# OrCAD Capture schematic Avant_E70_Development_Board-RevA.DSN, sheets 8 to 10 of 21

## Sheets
8 Bank-6 LED,SWITCH: size C; title: Bank-6 LED,SWITCH
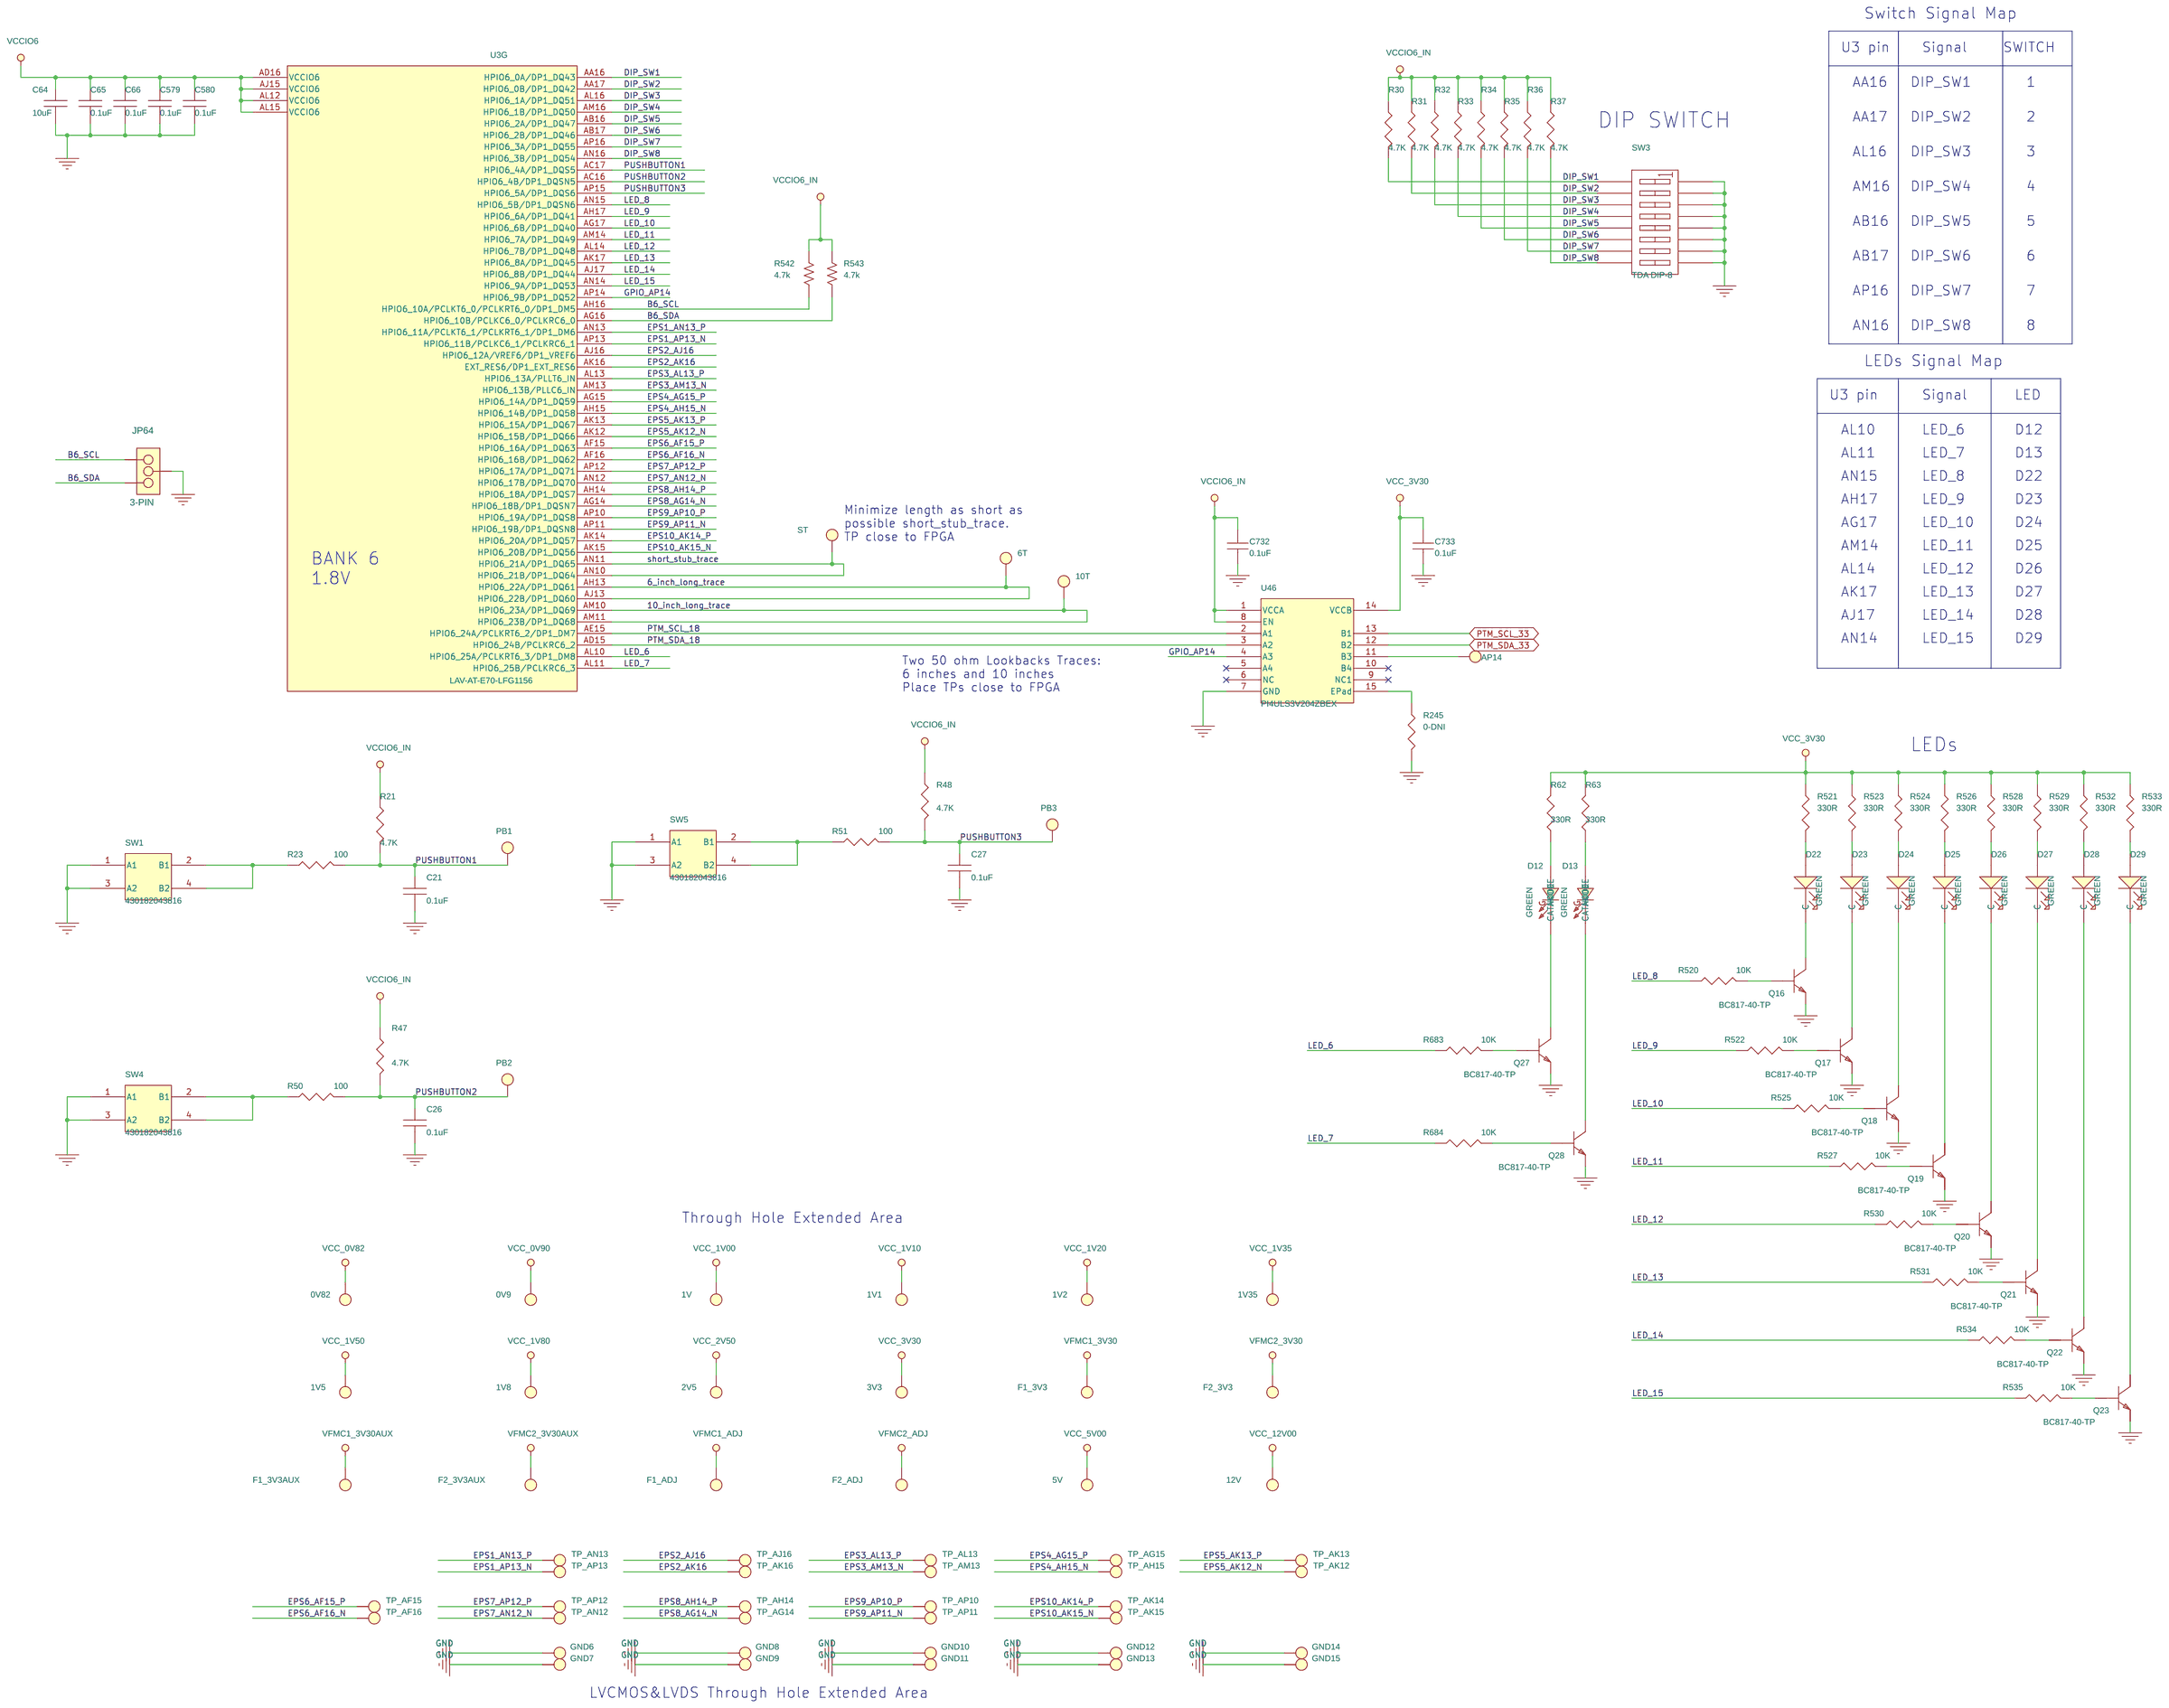
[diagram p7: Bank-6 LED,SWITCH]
9 Bank-7,8 FMC2: size B; title: Bank-7,8 FMC2
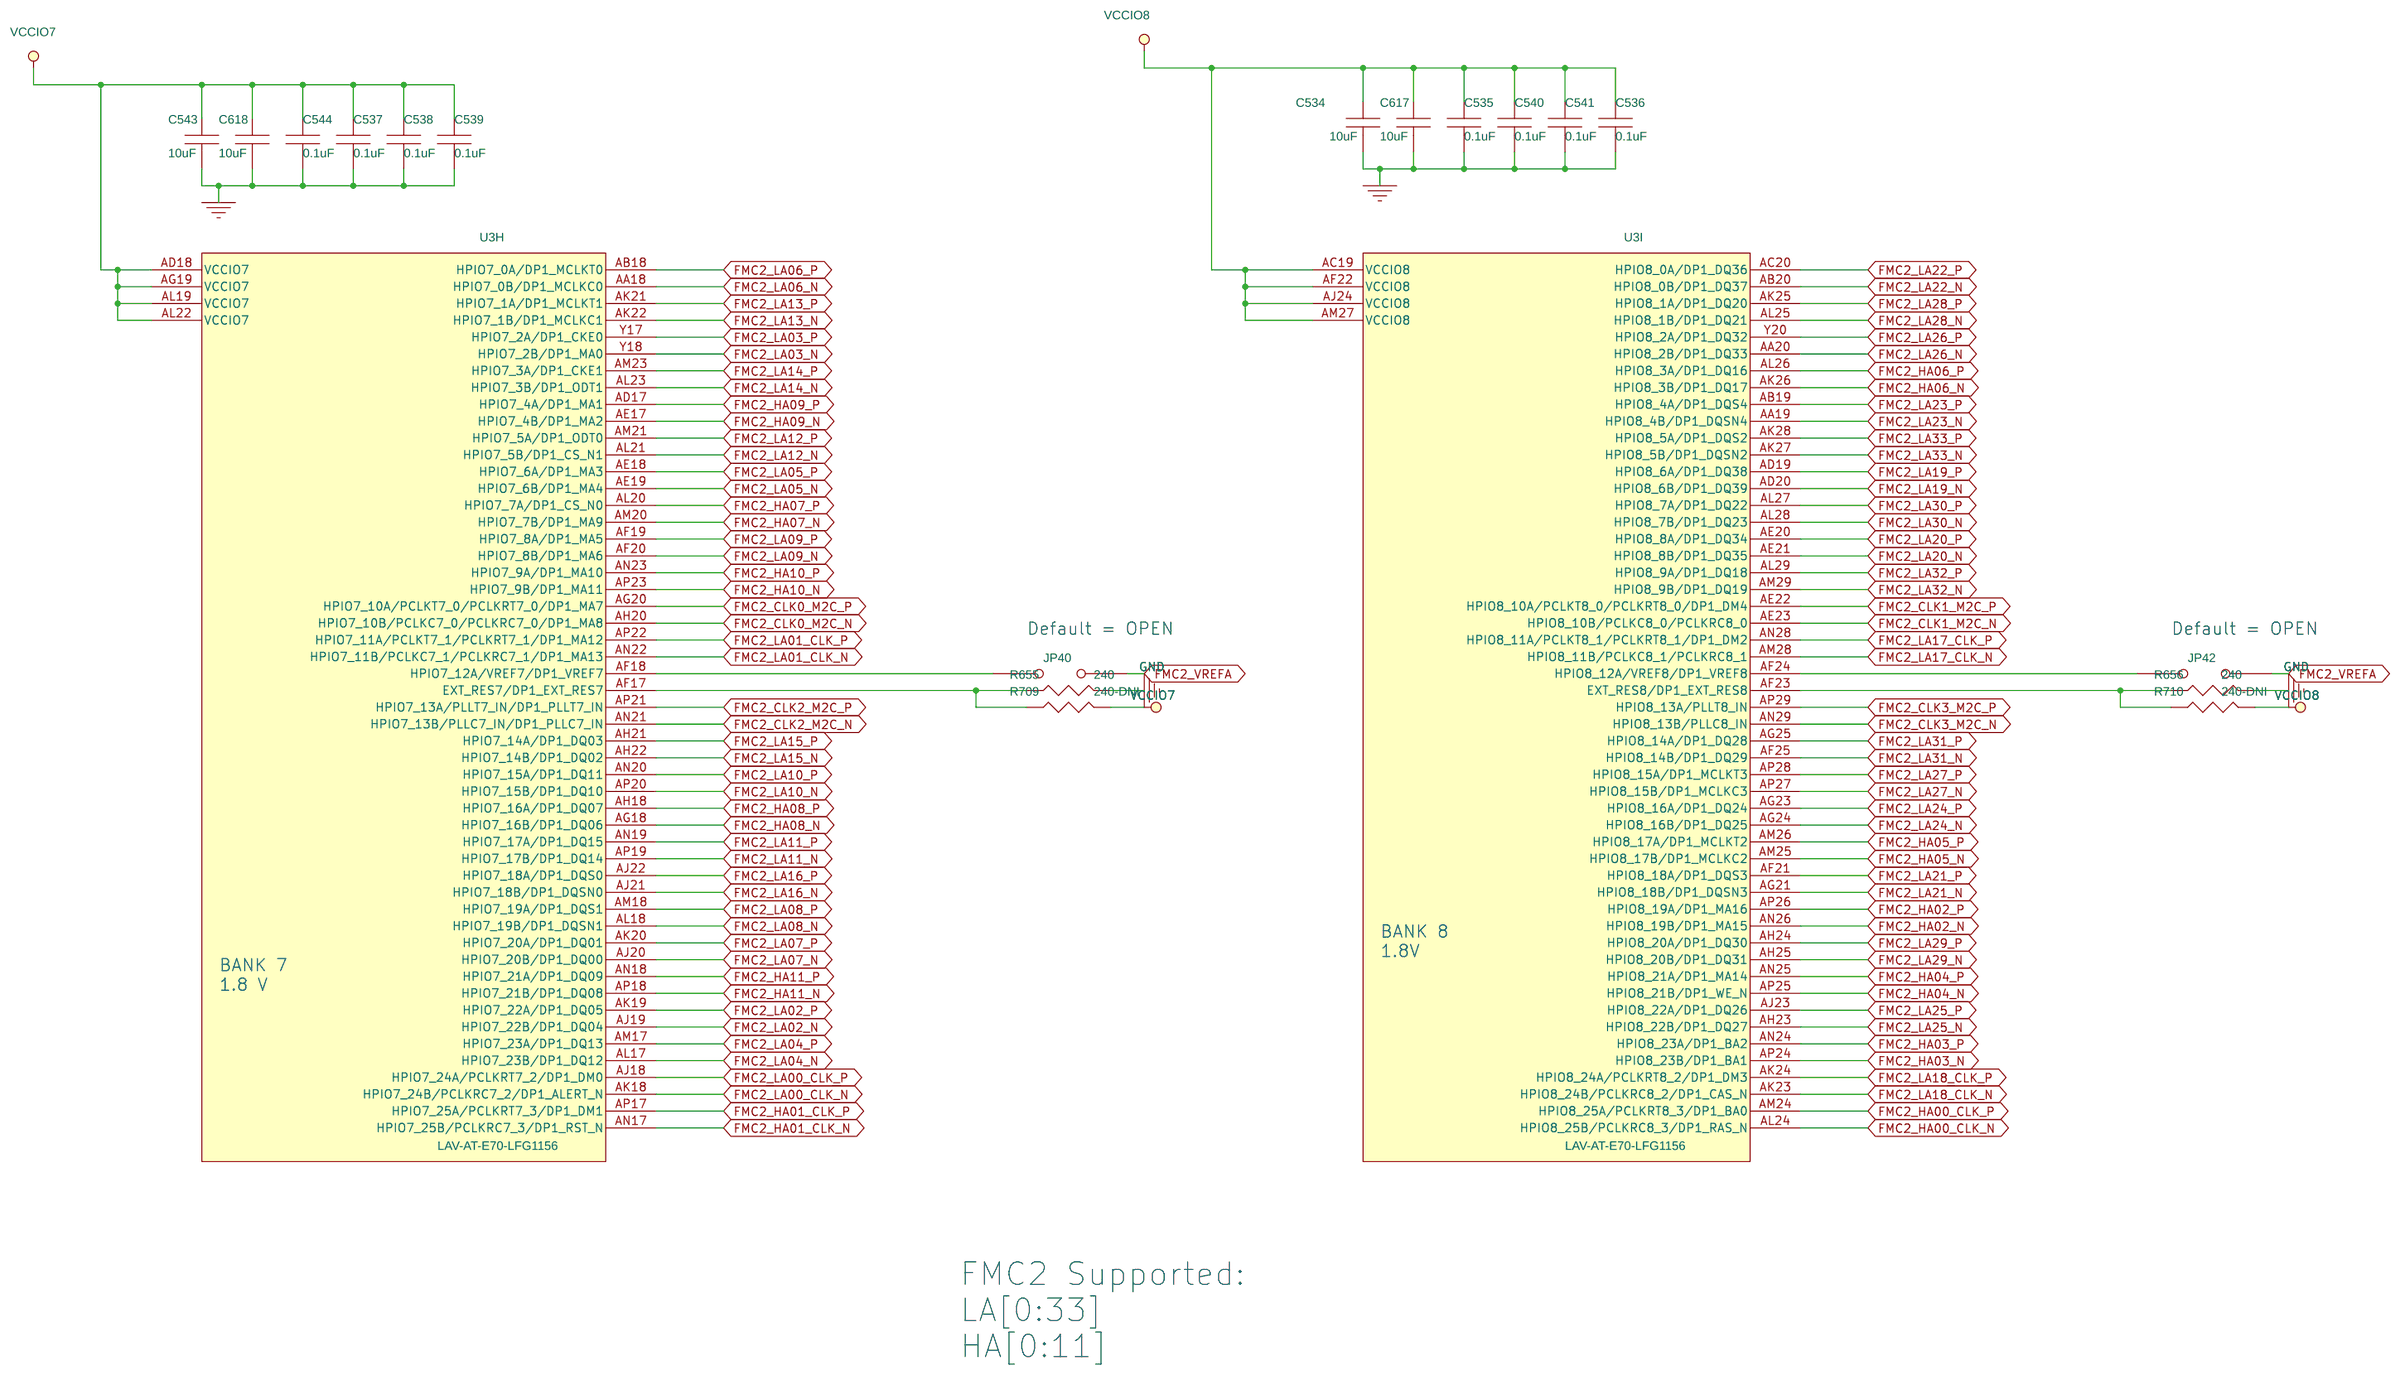
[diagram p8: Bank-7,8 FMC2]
10 FMC2 LA: size C; title: FMC2 LA
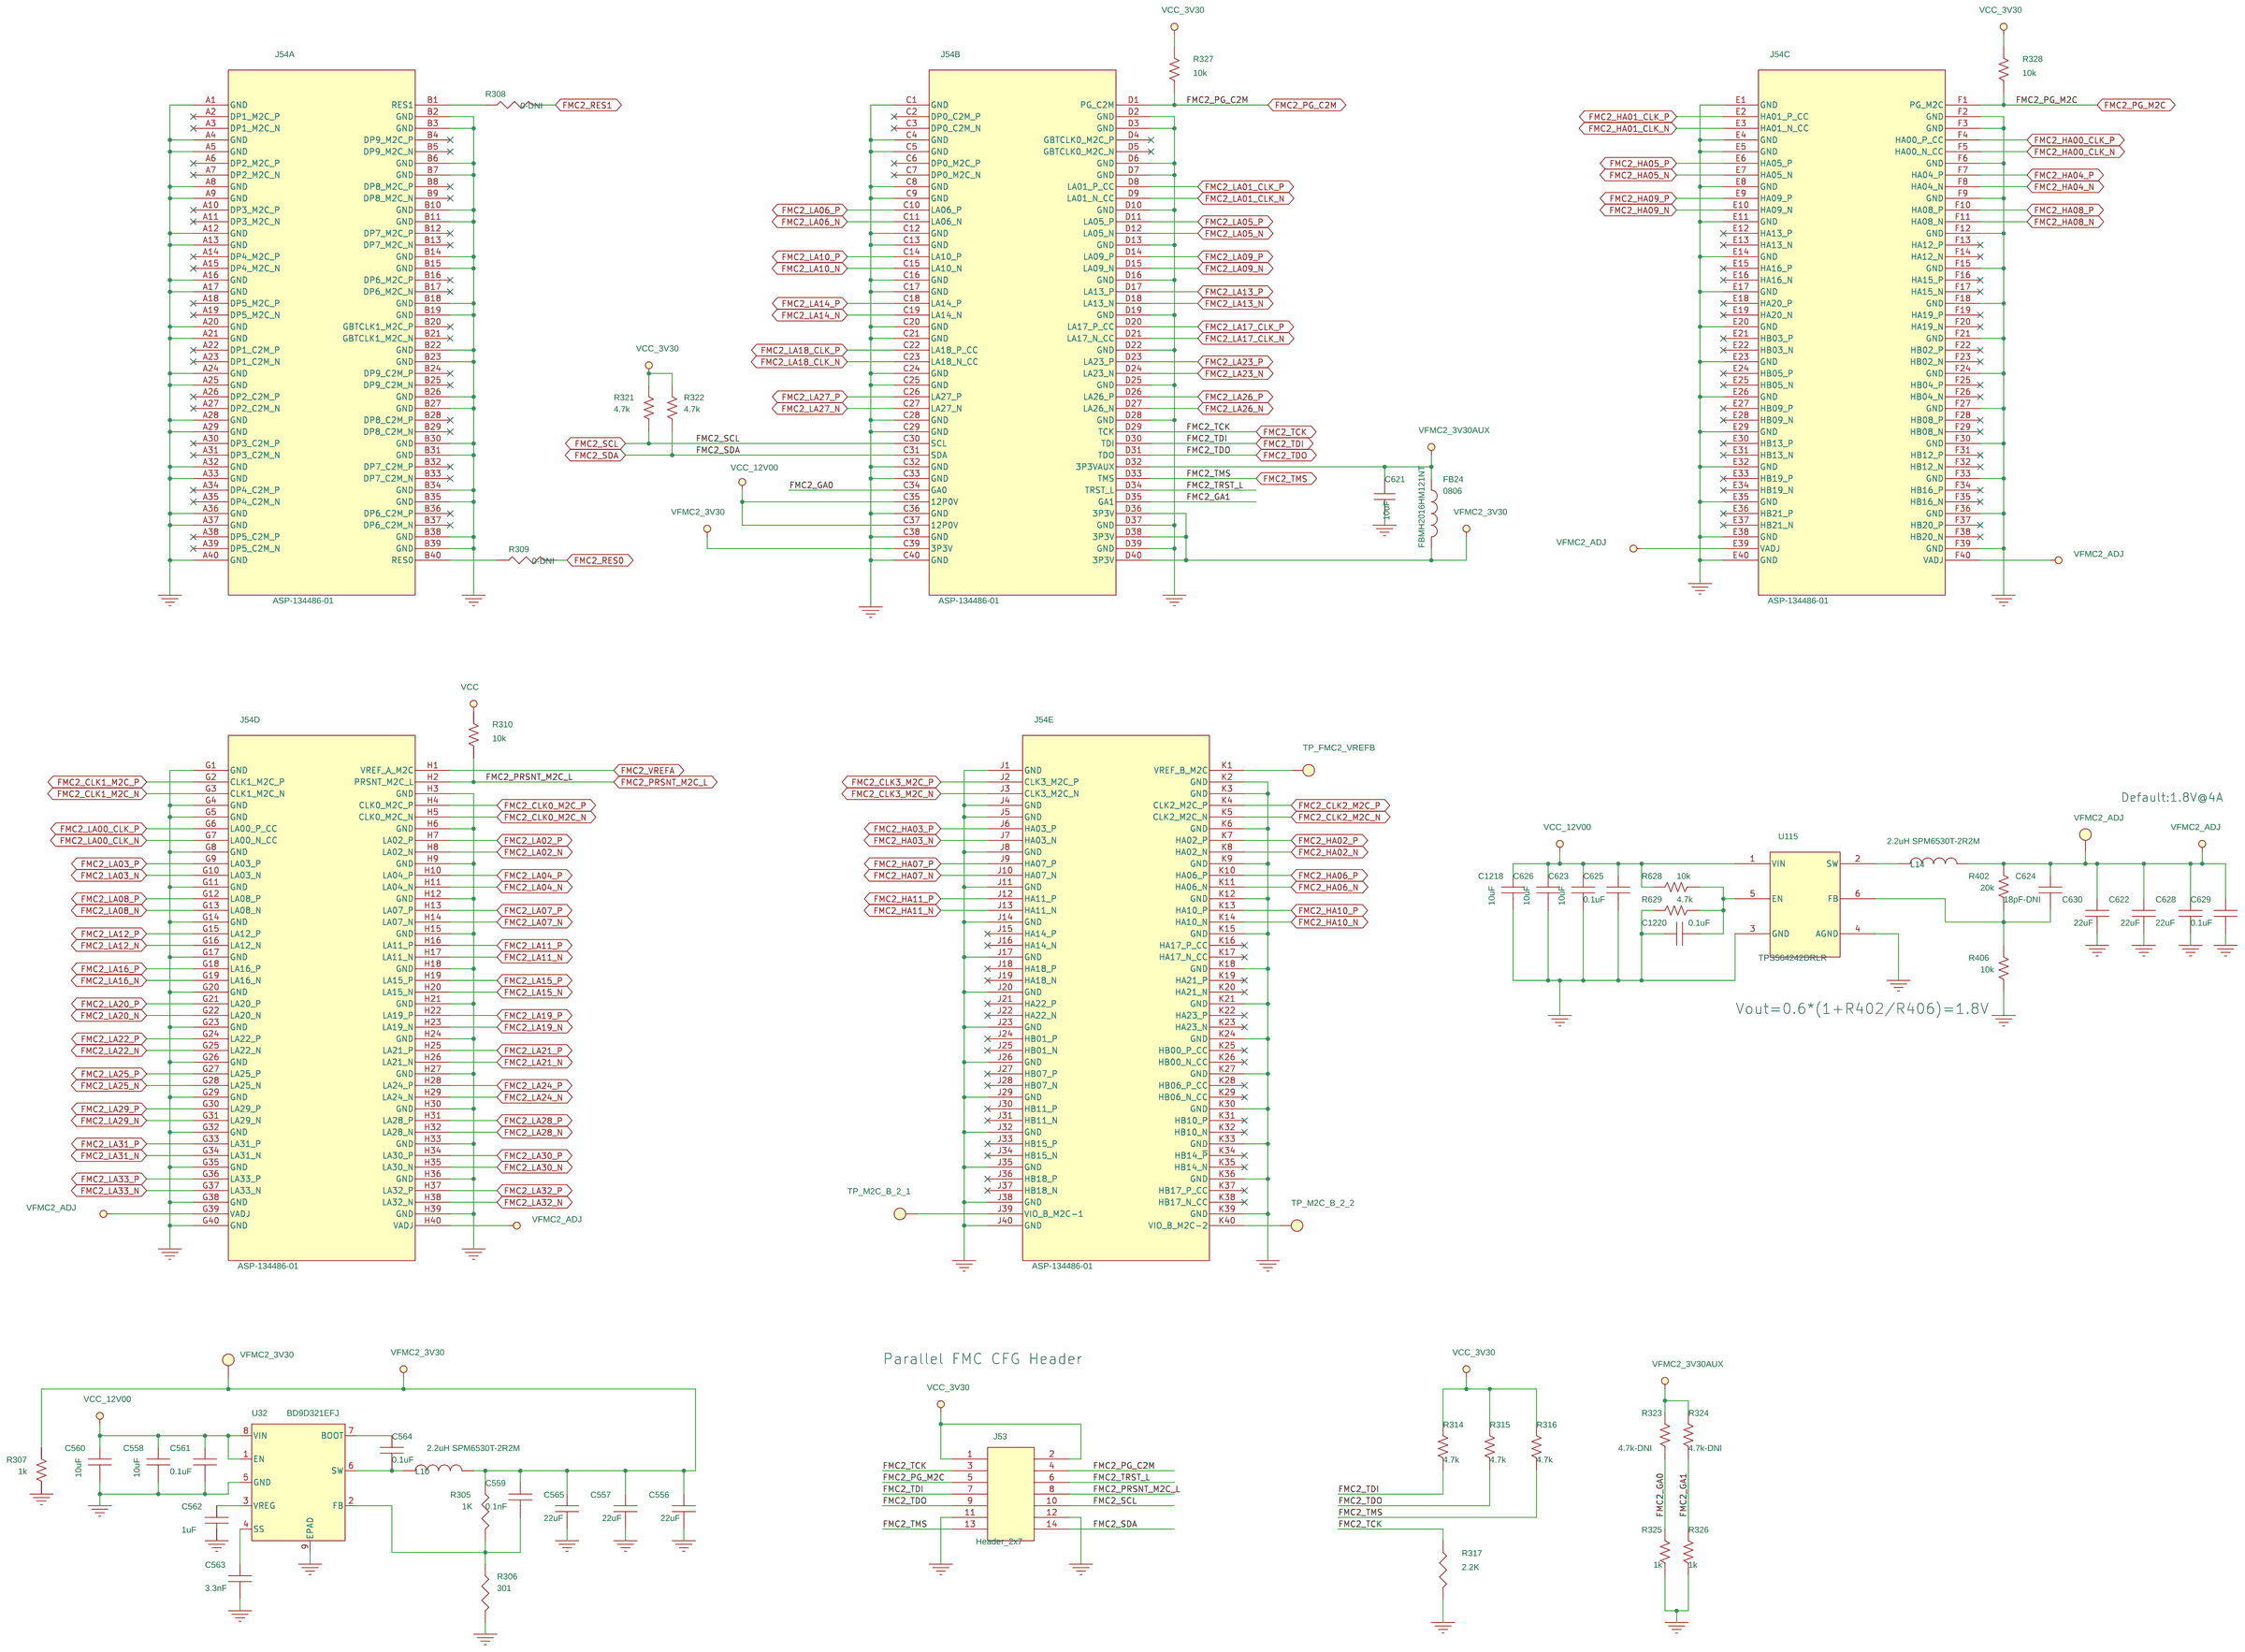
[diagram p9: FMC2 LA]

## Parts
sheet Bank-6 LED,SWITCH
0V9  T POINT R  [TP]
0V82  T POINT R  [TP]
1V  T POINT R  [TP]
1V1  T POINT R  [TP]
1V2  T POINT R  [TP]
1V5  T POINT R  [TP]
1V8  T POINT R  [TP]
1V35  T POINT R  [TP]
2V5  T POINT R  [TP]
3V3  T POINT R  [TP]
5V  T POINT R  [TP]
6T  VTTVREF  [TP_50]
10T  VTTVREF  [TP_50]
12V  T POINT R  [TP]
AP14  TestPoint_SMT  [TPC32]
C21  0.1uF  [C0201]
C26  0.1uF  [C0201]
C27  0.1uF  [C0201]
C64  10uF  [C0402]
C65  0.1uF  [C0201]
C66  0.1uF  [C0201]
C579  0.1uF  [C0201]
C580  0.1uF  [C0201]
C732  0.1uF  [C0402]
C733  0.1uF  [C0402]
D12  GREEN  [APT1608]
D13  GREEN  [APT1608]
D22  GREEN  [APT1608]
D23  GREEN  [APT1608]
D24  GREEN  [APT1608]
D25  GREEN  [APT1608]
D26  GREEN  [APT1608]
D27  GREEN  [APT1608]
D28  GREEN  [APT1608]
D29  GREEN  [APT1608]
F1_3V3  T POINT R  [TP]
F1_3V3AUX  T POINT R  [TP]
F1_ADJ  T POINT R  [TP]
F2_3V3  T POINT R  [TP]
F2_3V3AUX  T POINT R  [TP]
F2_ADJ  T POINT R  [TP]
GND6  T POINT R  [TP]
GND7  T POINT R  [TP]
GND8  T POINT R  [TP]
GND9  T POINT R  [TP]
GND10  T POINT R  [TP]
GND11  T POINT R  [TP]
GND12  T POINT R  [TP]
GND13  T POINT R  [TP]
GND14  T POINT R  [TP]
GND15  T POINT R  [TP]
JP64  3-PIN  [HDR254M-1X3]
PB1  TestPoint_SMT  [TPC32]
PB2  TestPoint_SMT  [TPC32]
PB3  TestPoint_SMT  [TPC32]
Q16  BC817-40-TP  [SOT23-3]
Q17  BC817-40-TP  [SOT23-3]
Q18  BC817-40-TP  [SOT23-3]
Q19  BC817-40-TP  [SOT23-3]
Q20  BC817-40-TP  [SOT23-3]
Q21  BC817-40-TP  [SOT23-3]
Q22  BC817-40-TP  [SOT23-3]
Q23  BC817-40-TP  [SOT23-3]
Q27  BC817-40-TP  [SOT23-3]
Q28  BC817-40-TP  [SOT23-3]
R21  4.7K  [R0603]
R23  100  [R0402]
R30  4.7K  [R0603]
R31  4.7K  [R0603]
R32  4.7K  [R0603]
R33  4.7K  [R0603]
R34  4.7K  [R0603]
R35  4.7K  [R0603]
R36  4.7K  [R0603]
R37  4.7K  [R0603]
R47  4.7K  [R0603]
R48  4.7K  [R0603]
R50  100  [R0402]
R51  100  [R0402]
R62  330R  [R0603]
R63  330R  [R0603]
R245  0-DNI  [R0402]
R520  10K  [R0603]
R521  330R  [R0603]
R522  10K  [R0603]
R523  330R  [R0603]
R524  330R  [R0603]
R525  10K  [R0603]
R526  330R  [R0603]
R527  10K  [R0603]
R528  330R  [R0603]
R529  330R  [R0603]
R530  10K  [R0603]
R531  10K  [R0603]
R532  330R  [R0603]
R533  330R  [R0603]
R534  10K  [R0603]
R535  10K  [R0603]
R542  4.7k  [R0603]
R543  4.7k  [R0603]
R683  10K  [R0603]
R684  10K  [R0603]
ST  VTTVREF  [TP_50]
SW1  430182043816  [430182043816]
SW3  TDA DIP-8  [TDA08H0SB1]
SW4  430182043816  [430182043816]
SW5  430182043816  [430182043816]
TP_AF15  T POINT R  [TP]
TP_AF16  T POINT R  [TP]
TP_AG14  T POINT R  [TP]
TP_AG15  T POINT R  [TP]
TP_AH14  T POINT R  [TP]
TP_AH15  T POINT R  [TP]
TP_AJ16  T POINT R  [TP]
TP_AK12  T POINT R  [TP]
TP_AK13  T POINT R  [TP]
TP_AK14  T POINT R  [TP]
TP_AK15  T POINT R  [TP]
TP_AK16  T POINT R  [TP]
TP_AL13  T POINT R  [TP]
TP_AM13  T POINT R  [TP]
TP_AN12  T POINT R  [TP]
TP_AN13  T POINT R  [TP]
TP_AP10  T POINT R  [TP]
TP_AP11  T POINT R  [TP]
TP_AP12  T POINT R  [TP]
TP_AP13  T POINT R  [TP]
U46  PI4ULS3V204ZBEX  [TQFN-14]
sheet Bank-7,8 FMC2
C534  10uF  [C0402]
C535  0.1uF  [C0201]
C536  0.1uF  [C0201]
C537  0.1uF  [C0201]
C538  0.1uF  [C0201]
C539  0.1uF  [C0201]
C540  0.1uF  [C0201]
C541  0.1uF  [C0201]
C543  10uF  [C0402]
C544  0.1uF  [C0201]
C617  10uF  [C0402]
C618  10uF  [C0402]
JP40  J-2 Pin Jumper  [0p1_2-Pin_TH]
JP42  J-2 Pin Jumper  [0p1_2-Pin_TH]
R655  240  [R0402]
R656  240  [R0402]
R709  240-DNI  [R0402]
R710  240-DNI  [R0402]
sheet Bank-12,13 PMODs
U3  LAV-AT-E70-LFG1156  [LAV-AT-500-L_1156]  (sections A,B,C,D,E,F,G,H,I,J,K,L,M,N,O,P,Q,R,S,T,U)
sheet FMC2 LA
C556  22uF  [C0603]
C557  22uF  [C0603]
C558  10uF  [C0603]
C559  0.1nF  [C0603]
C560  10uF  [C0603]
C561  0.1uF  [C0201]
C562  1uF  [C0603]
C563  3.3nF  [C0201]
C564  0.1uF  [C0201]
C565  22uF  [C0603]
C621  10uF  [C0402]
C622  22uF  [C0603]
C623  10uF  [C0603]
C624  18pF-DNI  [C0402]
C625  0.1uF  [C0201]
C626  10uF  [C0603]
C628  22uF  [C0603]
C629  0.1uF  [C0201]
C630  22uF  [C0603]
C1218  10uF  [C0603]
C1220  0.1uF  [C0201]
FB24  FBMH2016HM121NT  [0806]
J53  Header_2x7  [Header_2x7]
J54  ASP-134486-01  [ASP-134486-01]  (sections A,B,C,D,E)
L10  2.2uH SPM6530T-2R2M  [SPM6530T-2R2M]
L14  2.2uH SPM6530T-2R2M  [SPM6530T-2R2M]
R305  1K  [R0402]
R306  301  [R0402]
R307  1k  [R0603]
R308  0-DNI  [R0603]
R309  0-DNI  [R0603]
R310  10k  [R0603]
R314  4.7k  [R0603]
R315  4.7k  [R0603]
R316  4.7k  [R0603]
R317  2.2K  [R0603]
R321  4.7k  [R0603]
R322  4.7k  [R0603]
R323  4.7k-DNI  [R0603]
R324  4.7k-DNI  [R0603]
R325  1k  [R0603]
R326  1k  [R0603]
R327  10k  [R0603]
R328  10k  [R0603]
R402  20k  [R0603]
R406  10k  [R0603]
R628  10k  [R0603]
R629  4.7k  [R0603]
TP_FMC2_VREFB  TestPoint  [TP50]
TP_M2C_B_2_1  TestPoint  [TP50]
TP_M2C_B_2_2  TestPoint  [TP50]
U32  BD9D321EFJ  [HTSOP_8_BD9D321]
U115  TPS564242DRLR  [SOT-563-6]
VFMC2_3V30  VTTVREF  [TP_50]
VFMC2_ADJ  TestPoint_SMT  [TPC32]

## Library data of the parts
0V9 1V5 F2_3V3 = T_POINT_R_0: Assy: DNI; COMPFIXED: NO; COMPGROUP: 0; COMPHEIGHT: 0.000; COMPKEY: NO; COMPLOC: [400.000,3800.000]; COMPLOCKED: NO; COMPROT: 0; COMPSIDE: TOP; DECOUPLER: NO; MEMORY: NO
0V82 1V35 F1_3V3 = T_POINT_R_0: Assy: DNI; COMPFIXED: NO; COMPGROUP: 0; COMPHEIGHT: 0.000; COMPKEY: NO; COMPLOC: [300.000,3800.000]; COMPLOCKED: NO; COMPROT: 0; COMPSIDE: TOP; DECOUPLER: NO; MEMORY: NO
1V 1V8 5V TP_AK12 = T_POINT_R_0: Assy: DNI; COMPFIXED: NO; COMPGROUP: 0; COMPHEIGHT: 0.000; COMPKEY: NO; COMPLOC: [500.000,3800.000]; COMPLOCKED: NO; COMPROT: 0; COMPSIDE: TOP; DECOUPLER: NO; MEMORY: NO
1V1 1V2 2V5 3V3 12V F1_3V3AUX F1_ADJ F2_3V3AUX F2_ADJ = T_POINT_R_0: Assy: DNI; COMPFIXED: NO; COMPGROUP: 0; COMPHEIGHT: 0.000; COMPKEY: NO; COMPLOC: [700.000,3800.000]; COMPLOCKED: NO; COMPROT: 0; COMPSIDE: TOP; DECOUPLER: NO; MEMORY: NO
6T 10T ST VFMC2_3V30 = TP_SMD
AP14 PB1-PB3 VFMC2_ADJ = T_POINT_R: Assy: DNI
C21 C26 C27 = 0u1_0402: CAP CER 0.1UF 16V 10% X7R 0402
C64 C534 C543 C617 C618 = 10uF_0603
C65 C66 C535-C541 C544 C561 C564 C579 C580 C625 C629 C1220 = 0u1_0402: CAP CER 0.1UF 25V 10% X5R 0201; Manufacturer: Murata; Manufacturer Part Number: GRM033R61E104KE14J
C732 C733 = C-0402_0.1uF_10V_X5R_MURATA
D12 D13 = LED-SMT1206_GREEN_3
D22-D29 = D-_RED_LED_0: Manufacturer Part Number: 150060RS75000
GND6-GND15 = T_POINT_R_0: Assy: DNI; COMPFIXED: NO; COMPGROUP: 0; COMPHEIGHT: 0.000; COMPKEY: NO; COMPLOC: [300.000,3000.000]; COMPLOCKED: NO; COMPROT: 0; COMPSIDE: TOP; DECOUPLER: NO; MEMORY: NO
JP64 = 3-PINS_0.1_SINGLE_LINE_PIN
Q16-Q23 Q27 Q28 = TRANS_NPN_45V_0_0.8A_SOT-23: TRANS NPN 45V 0.8A SOT-23; Manufacturer: Micro Commercial Co
R21 R30-R37 R47 R48 = 5k1_0402: RES 4.70K OHM 1/10W 1% 0603 SMD; Digikey P/N: 541-4.70KHTR-ND; Manufacturer: Vishay; Manufacturer Part Number: CRCW06034K70FKEA
R23 R50 R51 = RES_10K_1W16_0402_5P: RES SMD 100 OHM 1% 1/10W 0402; Digikey P/N: RMCF0603JT10K0TR-ND; MFG: Pansonic; MFG P/N: ERJ-2RKF1000X; Manufacturer: Pansonic; Manufacturer Part Number: ERJ-2RKF1000X; Wattage: 1/10W
R62 R63 = 1k_0402: RES 1K OHM 1/10W 1% 0603 SMD; Digikey P/N: 311-1.00KHRCT-ND; Manufacturer Part Number: RC0603FR-071KL
R245 = R0402_0R_DNI_PANASONIC
R520 R522 R525 R527 R530 R531 R534 R535 R683 R684 = R_10K_0603: Manufacturer Part Number: RC1608F103CS
R521 R523 R524 R526 R528 R529 R532 R533 = R_330R_0603: Manufacturer Part Number: ERJ-3EKF3300V
R321 R542 = R: RES SMD 1K OHM 1% 1/10W 0402; COMPFIXED: NO; COMPGROUP: 0; COMPHEIGHT: 0.000; COMPKEY: NO; COMPLOC: [970.000,1160.000]; COMPLOCKED: NO; COMPROT: 180; COMPSIDE: TOP; DECOUPLER: NO; FPLIST: AX/RC05,SM/R_0603; MEMORY: NO; Manufacturer: Panasonic; Manufacturer Part Number: ERJ-2RKF1001X
R307 R310 R314-R316 R322-R328 R402 R406 R543 R628 R629 = R: RES SMD 4.7K OHM 5% 1/10W 0402; COMPFIXED: NO; COMPGROUP: 0; COMPHEIGHT: 0.000; COMPKEY: NO; COMPLOC: [970.000,1160.000]; COMPLOCKED: NO; COMPROT: 180; COMPSIDE: TOP; DECOUPLER: NO; FPLIST: AX/RC05,SM/R_0603; MEMORY: NO; MFG: Panasonic; MFG P/N: ERJ-2GEJ472X; Manufacturer: Panasonic; Manufacturer Part Number: ERJ-2GEJ472X
SW1 SW4 SW5 = EVQP0_0: SWITCH TACTILE SPST-NO 0.05A 12V; Cost Ea/1k: $ 0.11025 (1000-4999), 0.09135 (5000+); Digikey P/N: CKN9112TR-ND; Distributor: Digi-Key; MFG: C&K Components; Manufacturer: C&K Components
SW3 = SW_DIP-8
TP_AF15 = T_POINT_R_0: Assy: DNI; COMPFIXED: NO; COMPGROUP: 0; COMPHEIGHT: 0.000; COMPKEY: NO; COMPLOC: [500.000,3700.000]; COMPLOCKED: NO; COMPROT: 0; COMPSIDE: TOP; DECOUPLER: NO; MEMORY: NO
TP_AF16 = T_POINT_R_0: Assy: DNI; COMPFIXED: NO; COMPGROUP: 0; COMPHEIGHT: 0.000; COMPKEY: NO; COMPLOC: [500.000,3600.000]; COMPLOCKED: NO; COMPROT: 0; COMPSIDE: TOP; DECOUPLER: NO; MEMORY: NO
TP_AG14 TP_AK15 TP_AP11 = T_POINT_R_0: Assy: DNI; COMPFIXED: NO; COMPGROUP: 0; COMPHEIGHT: 0.000; COMPKEY: NO; COMPLOC: [500.000,3200.000]; COMPLOCKED: NO; COMPROT: 0; COMPSIDE: TOP; DECOUPLER: NO; MEMORY: NO
TP_AG15 = T_POINT_R_0: Assy: DNI; COMPFIXED: NO; COMPGROUP: 0; COMPHEIGHT: 0.000; COMPKEY: NO; COMPLOC: [600.000,3100.000]; COMPLOCKED: NO; COMPROT: 0; COMPSIDE: TOP; DECOUPLER: NO; MEMORY: NO
TP_AH14 TP_AK14 TP_AP10 = T_POINT_R_0: Assy: DNI; COMPFIXED: NO; COMPGROUP: 0; COMPHEIGHT: 0.000; COMPKEY: NO; COMPLOC: [500.000,3300.000]; COMPLOCKED: NO; COMPROT: 0; COMPSIDE: TOP; DECOUPLER: NO; MEMORY: NO
TP_AH15 = T_POINT_R_0: Assy: DNI; COMPFIXED: NO; COMPGROUP: 0; COMPHEIGHT: 0.000; COMPKEY: NO; COMPLOC: [600.000,3000.000]; COMPLOCKED: NO; COMPROT: 0; COMPSIDE: TOP; DECOUPLER: NO; MEMORY: NO
TP_AJ16 = T_POINT_R_0: Assy: DNI; COMPFIXED: NO; COMPGROUP: 0; COMPHEIGHT: 0.000; COMPKEY: NO; COMPLOC: [600.000,3500.000]; COMPLOCKED: NO; COMPROT: 0; COMPSIDE: TOP; DECOUPLER: NO; MEMORY: NO
TP_AK13 = T_POINT_R_0: Assy: DNI; COMPFIXED: NO; COMPGROUP: 0; COMPHEIGHT: 0.000; COMPKEY: NO; COMPLOC: [600.000,2900.000]; COMPLOCKED: NO; COMPROT: 0; COMPSIDE: TOP; DECOUPLER: NO; MEMORY: NO
TP_AK16 = T_POINT_R_0: Assy: DNI; COMPFIXED: NO; COMPGROUP: 0; COMPHEIGHT: 0.000; COMPKEY: NO; COMPLOC: [600.000,3400.000]; COMPLOCKED: NO; COMPROT: 0; COMPSIDE: TOP; DECOUPLER: NO; MEMORY: NO
TP_AL13 = T_POINT_R_0: Assy: DNI; COMPFIXED: NO; COMPGROUP: 0; COMPHEIGHT: 0.000; COMPKEY: NO; COMPLOC: [600.000,3300.000]; COMPLOCKED: NO; COMPROT: 0; COMPSIDE: TOP; DECOUPLER: NO; MEMORY: NO
TP_AM13 = T_POINT_R_0: Assy: DNI; COMPFIXED: NO; COMPGROUP: 0; COMPHEIGHT: 0.000; COMPKEY: NO; COMPLOC: [600.000,3200.000]; COMPLOCKED: NO; COMPROT: 0; COMPSIDE: TOP; DECOUPLER: NO; MEMORY: NO
TP_AN12 = T_POINT_R_0: Assy: DNI; COMPFIXED: NO; COMPGROUP: 0; COMPHEIGHT: 0.000; COMPKEY: NO; COMPLOC: [500.000,3400.000]; COMPLOCKED: NO; COMPROT: 0; COMPSIDE: TOP; DECOUPLER: NO; MEMORY: NO
TP_AN13 = T_POINT_R_0: Assy: DNI; COMPFIXED: NO; COMPGROUP: 0; COMPHEIGHT: 0.000; COMPKEY: NO; COMPLOC: [600.000,3700.000]; COMPLOCKED: NO; COMPROT: 0; COMPSIDE: TOP; DECOUPLER: NO; MEMORY: NO
TP_AP12 = T_POINT_R_0: Assy: DNI; COMPFIXED: NO; COMPGROUP: 0; COMPHEIGHT: 0.000; COMPKEY: NO; COMPLOC: [500.000,3500.000]; COMPLOCKED: NO; COMPROT: 0; COMPSIDE: TOP; DECOUPLER: NO; MEMORY: NO
TP_AP13 = T_POINT_R_0: Assy: DNI; COMPFIXED: NO; COMPGROUP: 0; COMPHEIGHT: 0.000; COMPKEY: NO; COMPLOC: [600.000,3600.000]; COMPLOCKED: NO; COMPROT: 0; COMPSIDE: TOP; DECOUPLER: NO; MEMORY: NO
U46 = U-PI4ULS3V204ZBEX
JP40 JP42 = J-2_Pin_Jumper: Manufacturer Part Number: 22-28-4020
R655 R656 R709 R710 = 0R_0603: RES 0.0 OHM 1/10W JUMP 0603 SMD
U3 = LAV-AT-E70-LFG1156_6
C556 C557 C565 C622 C630 = 10uF_0603: CAP CER 22UF 10V X5R 0603; Manufacturer: Murata; Manufacturer Part Number: GRM188R61A226ME15D
C558 C560 C623 C626 C1218 = 10uF_0603: CAP CER 10UF 25V X5R 1206; Manufacturer Part Number: TMK316BJ106KL-T
C559 C624 = 10uF_0603: CAP CER 100PF 50V C0G/NPO 0603; Manufacturer: Yageo; Manufacturer Part Number: CC0603JRNPO9BN101
C562 C628 = 10uF_0603: CAP CER 1UF 25V 10% X7R 0603; Manufacturer Part Number: TMK107B7105KA-T
C563 = 0u1_0402: CAP CER 3300PF 25V X7R 0201; Manufacturer: Murata; Manufacturer Part Number: GRM033R71E332KA12D
C621 = CAP_NP: COMPFIXED: NO; COMPGROUP: 0; COMPHEIGHT: 0.000; COMPKEY: NO; COMPLOC: [1820.000,2015.000]; COMPLOCKED: NO; COMPROT: 270; COMPSIDE: TOP; DECOUPLER: NO; FPLIST: SM/C_0402; MEMORY: NO
FB24 = FB_0806_120R_TaiyoYuden
J53 = Header_2x7
J54 = ASP-134486-01_0
L10 L14 = INDUCTOR_0
R305 = R0402_1K_1%_Yageo: Manufacturer Part Number: RC0402FR-071KL
R306 = R0402_301R_1%_Yageo: Manufacturer Part Number: RC0402FR-07301RL
R308 R309 R317 = 5k1_0402: Digikey P/N: 541-2.20KHTR-ND; Manufacturer: Vishay; Manufacturer Part Number: CRCW06032K20FKEA
TP_FMC2_VREFB TP_M2C_B_2_1 TP_M2C_B_2_2 = T_POINT_R
U32 = BD9D321EFJ
U115 = TPS564242DRLR

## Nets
GND: C21.2 C26.2 C27.2 C64.2 C65.2 C66.2 C534.2 C535.2 C536.2 C537.2 C538.2 C539.2 C540.2 C541.2 C543.2 C544.2 C556.2 C557.2 C558.2 C560.2 C561.2 C562.2 C563.2 C565.2 C579.2 C580.2 C617.2 C618.2 C621.1 C622.2 C623.2 C625.2 C626.2 C628.2 C629.2 C630.2 C732.2 C733.2 C1218.2 C1220.1 GND6.1(TP) GND7.1(TP) GND8.1(TP) GND9.1(TP) GND10.1(TP) GND11.1(TP) GND12.1(TP) GND13.1(TP) GND14.1(TP) GND15.1(TP) J53.11 J53.12 J54.A1(GND) J54.A4(GND) J54.A5(GND) J54.A8(GND) J54.A9(GND) J54.A12(GND) J54.A13(GND) J54.A16(GND) J54.A17(GND) J54.A20(GND) J54.A21(GND) J54.A24(GND) J54.A25(GND) J54.A28(GND) J54.A29(GND) J54.A32(GND) J54.A33(GND) J54.A36(GND) J54.A37(GND) J54.A40(GND) J54.B2(GND) J54.B3(GND) J54.B6(GND) J54.B7(GND) J54.B10(GND) J54.B11(GND) J54.B14(GND) J54.B15(GND) J54.B18(GND) J54.B19(GND) J54.B22(GND) J54.B23(GND) J54.B26(GND) J54.B27(GND) J54.B30(GND) J54.B31(GND) J54.B34(GND) J54.B35(GND) J54.B38(GND) J54.B39(GND) J54.C1(GND) J54.C4(GND) J54.C5(GND) J54.C8(GND) J54.C9(GND) J54.C12(GND) J54.C13(GND) J54.C16(GND) J54.C17(GND) J54.C20(GND) J54.C21(GND) J54.C24(GND) J54.C25(GND) J54.C28(GND) J54.C29(GND) J54.C32(GND) J54.C33(GND) J54.C36(GND) J54.C38(GND) J54.C40(GND) J54.D2(GND) J54.D3(GND) J54.D6(GND) J54.D7(GND) J54.D10(GND) J54.D13(GND) J54.D16(GND) J54.D19(GND) J54.D22(GND) J54.D25(GND) J54.D28(GND) J54.D37(GND) J54.D39(GND) J54.E1(GND) J54.E4(GND) J54.E5(GND) J54.E8(GND) J54.E11(GND) J54.E14(GND) J54.E17(GND) J54.E20(GND) J54.E23(GND) J54.E26(GND) J54.E29(GND) J54.E32(GND) J54.E35(GND) J54.E38(GND) J54.E40(GND) J54.F2(GND) J54.F3(GND) J54.F6(GND) J54.F9(GND) J54.F12(GND) J54.F15(GND) J54.F18(GND) J54.F21(GND) J54.F24(GND) J54.F27(GND) J54.F30(GND) J54.F33(GND) J54.F36(GND) J54.F39(GND) J54.G1(GND) J54.G4(GND) J54.G5(GND) J54.G8(GND) J54.G11(GND) J54.G14(GND) J54.G17(GND) J54.G20(GND) J54.G23(GND) J54.G26(GND) J54.G29(GND) J54.G32(GND) J54.G35(GND) J54.G38(GND) J54.G40(GND) J54.H3(GND) J54.H6(GND) J54.H9(GND) J54.H12(GND) J54.H15(GND) J54.H18(GND) J54.H21(GND) J54.H24(GND) J54.H27(GND) J54.H30(GND) J54.H33(GND) J54.H36(GND) J54.H39(GND) J54.J1(GND) J54.J4(GND) J54.J5(GND) J54.J8(GND) J54.J11(GND) J54.J14(GND) J54.J17(GND) J54.J20(GND) J54.J23(GND) J54.J26(GND) J54.J29(GND) J54.J32(GND) J54.J35(GND) J54.J38(GND) J54.J40(GND) J54.K2(GND) J54.K3(GND) J54.K6(GND) J54.K9(GND) J54.K12(GND) J54.K15(GND) J54.K18(GND) J54.K21(GND) J54.K24(GND) J54.K27(GND) J54.K30(GND) J54.K33(GND) J54.K36(GND) J54.K39(GND) JP64.2 Q16.E Q17.E Q18.E Q19.E Q20.E Q21.E Q22.E Q23.E Q27.E Q28.E R245.2 R306.2 R307.1 R317.2 R325.1 R326.1 R406.1 R629.2 R655.2 R656.2 SW1.1(A1) SW1.3(A2) SW3.9(B8) SW3.10(B7) SW3.11(B6) SW3.12(B5) SW3.13(B4) SW3.14(B3) SW3.15(B2) SW3.16(B1) SW4.1(A1) SW4.3(A2) SW5.1(A1) SW5.3(A2) U32.5(GND) U32.9(EPAD) U46.7(GND) U115.3(GND) U115.4(AGND) ; also on sheet 3 4 5 6 7 11 12 13 14 15 16 17 18 19 20
VCC_0V82: 0V82.1(TP) ; also on sheet 15 17
VCC_0V90: 0V9.1(TP) ; also on sheet 14 16
VCC_1V00: 1V.1(TP) ; also on sheet 14 16
VCC_1V10: 1V1.1(TP) ; also on sheet 11 14 16
VCC_1V20: 1V2.1(TP) ; also on sheet 14 16 17
VCC_1V35: 1V35.1(TP) ; also on sheet 14 16
VCC_1V50: 1V5.1(TP) ; also on sheet 14 15 16
VCC_1V80: 1V8.1(TP) ; also on sheet 14 16 19
VCC_2V50: 2V5.1(TP) ; also on sheet 14 16
VCC_3V30: 3V3.1(TP) C733.1 J53.1 J53.2 R62.2 R63.2 R310.2 R314.2 R315.2 R316.2 R321.2 R322.2 R327.2 R328.2 R521.2 R523.2 R524.2 R526.2 R528.2 R529.2 R532.2 R533.2 U46.14(VCCB) ; also on sheet 3 7 11 13 14 16 17
VCC_5V00: 5V.1(TP) ; also on sheet 13 16 17
VCC_12V00: 12V.1(TP) C558.1 C560.1 C561.1 C623.1 C625.1 C626.1 C1218.1 J54.C35(12P0V) J54.C37(12P0V) R628.2 U32.1(EN) U32.8(VIN) U115.1(VIN) ; also on sheet 7 17
VCCIO6: C64.1 C65.1 C66.1 C579.1 C580.1 U3.AD16(VCCIO6) U3.AJ15(VCCIO6) U3.AL12(VCCIO6) U3.AL15(VCCIO6) ; also on sheet 14
VCCIO6_IN: C732.1 R21.1 R30.1 R31.1 R32.1 R33.1 R34.1 R35.1 R36.1 R37.1 R47.1 R48.1 R542.2 R543.2 U46.1(VCCA) U46.8(EN) ; also on sheet 14
VCCIO7: C537.1 C538.1 C539.1 C543.1 C544.1 C618.1 R709.2 U3.AD18(VCCIO7) U3.AG19(VCCIO7) U3.AL19(VCCIO7) U3.AL22(VCCIO7) ; also on sheet 14
VCCIO8: C534.1 C535.1 C536.1 C540.1 C541.1 C617.1 R710.2 U3.AC19(VCCIO8) U3.AF22(VCCIO8) U3.AJ24(VCCIO8) U3.AM27(VCCIO8) ; also on sheet 14
6_inch_long_trace: 6T.1 U3.AH13(HPIO6_22A/DP1_DQ61) U3.AJ13(HPIO6_22B/DP1_DQ60)
10_inch_long_trace: 10T.1 U3.AM10(HPIO6_23A/DP1_DQ69) U3.AM11(HPIO6_23B/DP1_DQ68)
B6_SCL: JP64.3 R542.1 U3.AH16(HPIO6_10A/PCLKT6_0/PCLKRT6_0/DP1_DM5)
B6_SDA: JP64.1 R543.1 U3.AG16(HPIO6_10B/PCLKC6_0/PCLKRC6_0)
DIP_SW1: R30.2 SW3.1(A1) U3.AA16(HPIO6_0A/DP1_DQ43)
DIP_SW2: R31.2 SW3.2(A2) U3.AA17(HPIO6_0B/DP1_DQ42)
DIP_SW3: R32.2 SW3.3(A3) U3.AL16(HPIO6_1A/DP1_DQ51)
DIP_SW4: R33.2 SW3.4(A4) U3.AM16(HPIO6_1B/DP1_DQ50)
DIP_SW5: R34.2 SW3.5(A5) U3.AB16(HPIO6_2A/DP1_DQ47)
DIP_SW6: R35.2 SW3.6(A6) U3.AB17(HPIO6_2B/DP1_DQ46)
DIP_SW7: R36.2 SW3.7(A7) U3.AP16(HPIO6_3A/DP1_DQ55)
DIP_SW8: R37.2 SW3.8(A8) U3.AN16(HPIO6_3B/DP1_DQ54)
EPS1_AN13_P: TP_AN13.1(TP) U3.AN13(HPIO6_11A/PCLKT6_1/PCLKRT6_1/DP1_DM6)
EPS1_AP13_N: TP_AP13.1(TP) U3.AP13(HPIO6_11B/PCLKC6_1/PCLKRC6_1)
EPS2_AJ16: TP_AJ16.1(TP) U3.AJ16(HPIO6_12A/VREF6/DP1_VREF6)
EPS2_AK16: TP_AK16.1(TP) U3.AK16(EXT_RES6/DP1_EXT_RES6)
EPS3_AL13_P: TP_AL13.1(TP) U3.AL13(HPIO6_13A/PLLT6_IN)
EPS3_AM13_N: TP_AM13.1(TP) U3.AM13(HPIO6_13B/PLLC6_IN)
EPS4_AG15_P: TP_AG15.1(TP) U3.AG15(HPIO6_14A/DP1_DQ59)
EPS4_AH15_N: TP_AH15.1(TP) U3.AH15(HPIO6_14B/DP1_DQ58)
EPS5_AK12_N: TP_AK12.1(TP) U3.AK12(HPIO6_15B/DP1_DQ66)
EPS5_AK13_P: TP_AK13.1(TP) U3.AK13(HPIO6_15A/DP1_DQ67)
EPS6_AF15_P: TP_AF15.1(TP) U3.AF15(HPIO6_16A/DP1_DQ63)
EPS6_AF16_N: TP_AF16.1(TP) U3.AF16(HPIO6_16B/DP1_DQ62)
EPS7_AN12_N: TP_AN12.1(TP) U3.AN12(HPIO6_17B/DP1_DQ70)
EPS7_AP12_P: TP_AP12.1(TP) U3.AP12(HPIO6_17A/DP1_DQ71)
EPS8_AG14_N: TP_AG14.1(TP) U3.AG14(HPIO6_18B/DP1_DQSN7)
EPS8_AH14_P: TP_AH14.1(TP) U3.AH14(HPIO6_18A/DP1_DQS7)
EPS9_AP10_P: TP_AP10.1(TP) U3.AP10(HPIO6_19A/DP1_DQS8)
EPS9_AP11_N: TP_AP11.1(TP) U3.AP11(HPIO6_19B/DP1_DQSN8)
EPS10_AK14_P: TP_AK14.1(TP) U3.AK14(HPIO6_20A/DP1_DQ57)
EPS10_AK15_N: TP_AK15.1(TP) U3.AK15(HPIO6_20B/DP1_DQ56)
FMC2_CLK0_M2C_N: J54.H5(CLK0_M2C_N) U3.AH20(HPIO7_10B/PCLKC7_0/PCLKRC7_0/DP1_MA8)
FMC2_CLK0_M2C_P: J54.H4(CLK0_M2C_P) U3.AG20(HPIO7_10A/PCLKT7_0/PCLKRT7_0/DP1_MA7)
FMC2_CLK1_M2C_N: J54.G3(CLK1_M2C_N) U3.AE23(HPIO8_10B/PCLKC8_0/PCLKRC8_0)
FMC2_CLK1_M2C_P: J54.G2(CLK1_M2C_P) U3.AE22(HPIO8_10A/PCLKT8_0/PCLKRT8_0/DP1_DM4)
FMC2_CLK2_M2C_N: J54.K5(CLK2_M2C_N) U3.AN21(HPIO7_13B/PLLC7_IN/DP1_PLLC7_IN)
FMC2_CLK2_M2C_P: J54.K4(CLK2_M2C_P) U3.AP21(HPIO7_13A/PLLT7_IN/DP1_PLLT7_IN)
FMC2_CLK3_M2C_N: J54.J3(CLK3_M2C_N) U3.AN29(HPIO8_13B/PLLC8_IN)
FMC2_CLK3_M2C_P: J54.J2(CLK3_M2C_P) U3.AP29(HPIO8_13A/PLLT8_IN)
FMC2_GA0: J54.C34(GA0) R323.1 R325.2
FMC2_GA1: J54.D35(GA1) R324.1 R326.2
FMC2_HA00_CLK_N: J54.F5(HA00_N_CC) U3.AL24(HPIO8_25B/PCLKRC8_3/DP1_RAS_N)
FMC2_HA00_CLK_P: J54.F4(HA00_P_CC) U3.AM24(HPIO8_25A/PCLKRT8_3/DP1_BA0)
FMC2_HA01_CLK_N: J54.E3(HA01_N_CC) U3.AN17(HPIO7_25B/PCLKRC7_3/DP1_RST_N)
FMC2_HA01_CLK_P: J54.E2(HA01_P_CC) U3.AP17(HPIO7_25A/PCLKRT7_3/DP1_DM1)
FMC2_HA02_N: J54.K8(HA02_N) U3.AN26(HPIO8_19B/DP1_MA15)
FMC2_HA02_P: J54.K7(HA02_P) U3.AP26(HPIO8_19A/DP1_MA16)
FMC2_HA03_N: J54.J7(HA03_N) U3.AP24(HPIO8_23B/DP1_BA1)
FMC2_HA03_P: J54.J6(HA03_P) U3.AN24(HPIO8_23A/DP1_BA2)
FMC2_HA04_N: J54.F8(HA04_N) U3.AP25(HPIO8_21B/DP1_WE_N)
FMC2_HA04_P: J54.F7(HA04_P) U3.AN25(HPIO8_21A/DP1_MA14)
FMC2_HA05_N: J54.E7(HA05_N) U3.AM25(HPIO8_17B/DP1_MCLKC2)
FMC2_HA05_P: J54.E6(HA05_P) U3.AM26(HPIO8_17A/DP1_MCLKT2)
FMC2_HA06_N: J54.K11(HA06_N) U3.AK26(HPIO8_3B/DP1_DQ17)
FMC2_HA06_P: J54.K10(HA06_P) U3.AL26(HPIO8_3A/DP1_DQ16)
FMC2_HA07_N: J54.J10(HA07_N) U3.AM20(HPIO7_7B/DP1_MA9)
FMC2_HA07_P: J54.J9(HA07_P) U3.AL20(HPIO7_7A/DP1_CS_N0)
FMC2_HA08_N: J54.F11(HA08_N) U3.AG18(HPIO7_16B/DP1_DQ06)
FMC2_HA08_P: J54.F10(HA08_P) U3.AH18(HPIO7_16A/DP1_DQ07)
FMC2_HA09_N: J54.E10(HA09_N) U3.AE17(HPIO7_4B/DP1_MA2)
FMC2_HA09_P: J54.E9(HA09_P) U3.AD17(HPIO7_4A/DP1_MA1)
FMC2_HA10_N: J54.K14(HA10_N) U3.AP23(HPIO7_9B/DP1_MA11)
FMC2_HA10_P: J54.K13(HA10_P) U3.AN23(HPIO7_9A/DP1_MA10)
FMC2_HA11_N: J54.J13(HA11_N) U3.AP18(HPIO7_21B/DP1_DQ08)
FMC2_HA11_P: J54.J12(HA11_P) U3.AN18(HPIO7_21A/DP1_DQ09)
FMC2_LA00_CLK_N: J54.G7(LA00_N_CC) U3.AK18(HPIO7_24B/PCLKRC7_2/DP1_ALERT_N)
FMC2_LA00_CLK_P: J54.G6(LA00_P_CC) U3.AJ18(HPIO7_24A/PCLKRT7_2/DP1_DM0)
FMC2_LA01_CLK_N: J54.D9(LA01_N_CC) U3.AN22(HPIO7_11B/PCLKC7_1/PCLKRC7_1/DP1_MA13)
FMC2_LA01_CLK_P: J54.D8(LA01_P_CC) U3.AP22(HPIO7_11A/PCLKT7_1/PCLKRT7_1/DP1_MA12)
FMC2_LA02_N: J54.H8(LA02_N) U3.AJ19(HPIO7_22B/DP1_DQ04)
FMC2_LA02_P: J54.H7(LA02_P) U3.AK19(HPIO7_22A/DP1_DQ05)
FMC2_LA03_N: J54.G10(LA03_N) U3.Y18(HPIO7_2B/DP1_MA0)
FMC2_LA03_P: J54.G9(LA03_P) U3.Y17(HPIO7_2A/DP1_CKE0)
FMC2_LA04_N: J54.H11(LA04_N) U3.AL17(HPIO7_23B/DP1_DQ12)
FMC2_LA04_P: J54.H10(LA04_P) U3.AM17(HPIO7_23A/DP1_DQ13)
FMC2_LA05_N: J54.D12(LA05_N) U3.AE19(HPIO7_6B/DP1_MA4)
FMC2_LA05_P: J54.D11(LA05_P) U3.AE18(HPIO7_6A/DP1_MA3)
FMC2_LA06_N: J54.C11(LA06_N) U3.AA18(HPIO7_0B/DP1_MCLKC0)
FMC2_LA06_P: J54.C10(LA06_P) U3.AB18(HPIO7_0A/DP1_MCLKT0)
FMC2_LA07_N: J54.H14(LA07_N) U3.AJ20(HPIO7_20B/DP1_DQ00)
FMC2_LA07_P: J54.H13(LA07_P) U3.AK20(HPIO7_20A/DP1_DQ01)
FMC2_LA08_N: J54.G13(LA08_N) U3.AL18(HPIO7_19B/DP1_DQSN1)
FMC2_LA08_P: J54.G12(LA08_P) U3.AM18(HPIO7_19A/DP1_DQS1)
FMC2_LA09_N: J54.D15(LA09_N) U3.AF20(HPIO7_8B/DP1_MA6)
FMC2_LA09_P: J54.D14(LA09_P) U3.AF19(HPIO7_8A/DP1_MA5)
FMC2_LA10_N: J54.C15(LA10_N) U3.AP20(HPIO7_15B/DP1_DQ10)
FMC2_LA10_P: J54.C14(LA10_P) U3.AN20(HPIO7_15A/DP1_DQ11)
FMC2_LA11_N: J54.H17(LA11_N) U3.AP19(HPIO7_17B/DP1_DQ14)
FMC2_LA11_P: J54.H16(LA11_P) U3.AN19(HPIO7_17A/DP1_DQ15)
FMC2_LA12_N: J54.G16(LA12_N) U3.AL21(HPIO7_5B/DP1_CS_N1)
FMC2_LA12_P: J54.G15(LA12_P) U3.AM21(HPIO7_5A/DP1_ODT0)
FMC2_LA13_N: J54.D18(LA13_N) U3.AK22(HPIO7_1B/DP1_MCLKC1)
FMC2_LA13_P: J54.D17(LA13_P) U3.AK21(HPIO7_1A/DP1_MCLKT1)
FMC2_LA14_N: J54.C19(LA14_N) U3.AL23(HPIO7_3B/DP1_ODT1)
FMC2_LA14_P: J54.C18(LA14_P) U3.AM23(HPIO7_3A/DP1_CKE1)
FMC2_LA15_N: J54.H20(LA15_N) U3.AH22(HPIO7_14B/DP1_DQ02)
FMC2_LA15_P: J54.H19(LA15_P) U3.AH21(HPIO7_14A/DP1_DQ03)
FMC2_LA16_N: J54.G19(LA16_N) U3.AJ21(HPIO7_18B/DP1_DQSN0)
FMC2_LA16_P: J54.G18(LA16_P) U3.AJ22(HPIO7_18A/DP1_DQS0)
FMC2_LA17_CLK_N: J54.D21(LA17_N_CC) U3.AM28(HPIO8_11B/PCLKC8_1/PCLKRC8_1)
FMC2_LA17_CLK_P: J54.D20(LA17_P_CC) U3.AN28(HPIO8_11A/PCLKT8_1/PCLKRT8_1/DP1_DM2)
FMC2_LA18_CLK_N: J54.C23(LA18_N_CC) U3.AK23(HPIO8_24B/PCLKRC8_2/DP1_CAS_N)
FMC2_LA18_CLK_P: J54.C22(LA18_P_CC) U3.AK24(HPIO8_24A/PCLKRT8_2/DP1_DM3)
FMC2_LA19_N: J54.H23(LA19_N) U3.AD20(HPIO8_6B/DP1_DQ39)
FMC2_LA19_P: J54.H22(LA19_P) U3.AD19(HPIO8_6A/DP1_DQ38)
FMC2_LA20_N: J54.G22(LA20_N) U3.AE21(HPIO8_8B/DP1_DQ35)
FMC2_LA20_P: J54.G21(LA20_P) U3.AE20(HPIO8_8A/DP1_DQ34)
FMC2_LA21_N: J54.H26(LA21_N) U3.AG21(HPIO8_18B/DP1_DQSN3)
FMC2_LA21_P: J54.H25(LA21_P) U3.AF21(HPIO8_18A/DP1_DQS3)
FMC2_LA22_N: J54.G25(LA22_N) U3.AB20(HPIO8_0B/DP1_DQ37)
FMC2_LA22_P: J54.G24(LA22_P) U3.AC20(HPIO8_0A/DP1_DQ36)
FMC2_LA23_N: J54.D24(LA23_N) U3.AA19(HPIO8_4B/DP1_DQSN4)
FMC2_LA23_P: J54.D23(LA23_P) U3.AB19(HPIO8_4A/DP1_DQS4)
FMC2_LA24_N: J54.H29(LA24_N) U3.AG24(HPIO8_16B/DP1_DQ25)
FMC2_LA24_P: J54.H28(LA24_P) U3.AG23(HPIO8_16A/DP1_DQ24)
FMC2_LA25_N: J54.G28(LA25_N) U3.AH23(HPIO8_22B/DP1_DQ27)
FMC2_LA25_P: J54.G27(LA25_P) U3.AJ23(HPIO8_22A/DP1_DQ26)
FMC2_LA26_N: J54.D27(LA26_N) U3.AA20(HPIO8_2B/DP1_DQ33)
FMC2_LA26_P: J54.D26(LA26_P) U3.Y20(HPIO8_2A/DP1_DQ32)
FMC2_LA27_N: J54.C27(LA27_N) U3.AP27(HPIO8_15B/DP1_MCLKC3)
FMC2_LA27_P: J54.C26(LA27_P) U3.AP28(HPIO8_15A/DP1_MCLKT3)
FMC2_LA28_N: J54.H32(LA28_N) U3.AL25(HPIO8_1B/DP1_DQ21)
FMC2_LA28_P: J54.H31(LA28_P) U3.AK25(HPIO8_1A/DP1_DQ20)
FMC2_LA29_N: J54.G31(LA29_N) U3.AH25(HPIO8_20B/DP1_DQ31)
FMC2_LA29_P: J54.G30(LA29_P) U3.AH24(HPIO8_20A/DP1_DQ30)
FMC2_LA30_N: J54.H35(LA30_N) U3.AL28(HPIO8_7B/DP1_DQ23)
FMC2_LA30_P: J54.H34(LA30_P) U3.AL27(HPIO8_7A/DP1_DQ22)
FMC2_LA31_N: J54.G34(LA31_N) U3.AF25(HPIO8_14B/DP1_DQ29)
FMC2_LA31_P: J54.G33(LA31_P) U3.AG25(HPIO8_14A/DP1_DQ28)
FMC2_LA32_N: J54.H38(LA32_N) U3.AM29(HPIO8_9B/DP1_DQ19)
FMC2_LA32_P: J54.H37(LA32_P) U3.AL29(HPIO8_9A/DP1_DQ18)
FMC2_LA33_N: J54.G37(LA33_N) U3.AK27(HPIO8_5B/DP1_DQSN2)
FMC2_LA33_P: J54.G36(LA33_P) U3.AK28(HPIO8_5A/DP1_DQS2)
FMC2_PG_C2M: J53.4 J54.D1(PG_C2M) R327.1 ; also on sheet 12
FMC2_PG_M2C: J53.5 J54.F1(PG_M2C) R328.1 ; also on sheet 12
FMC2_PRSNT_M2C_L: J53.8 J54.H2(PRSNT_M2C_L) R310.1 ; also on sheet 12
FMC2_RES0: R309.2 ; also on sheet 12
FMC2_RES1: R308.2 ; also on sheet 12
FMC2_SCL: J53.10 J54.C30(SCL) R321.1 ; also on sheet 12
FMC2_SDA: J53.14 J54.C31(SDA) R322.1 ; also on sheet 12
FMC2_TCK: J53.3 J54.D29(TCK) R317.1 ; also on sheet 12
FMC2_TDI: J53.7 J54.D30(TDI) R314.1 ; also on sheet 12
FMC2_TDO: J53.9 J54.D31(TDO) R315.1 ; also on sheet 12
FMC2_TMS: J53.13 J54.D33(TMS) R316.1 ; also on sheet 12
FMC2_TRST_L: J53.6 J54.D34(TRST_L)
FMC2_VREFA: J54.H1(VREF_A_M2C) JP40.2 JP42.2
GPIO_AP14: U3.AP14(HPIO6_9B/DP1_DQ52) U46.4(A3)
LED_6: R683.2 U3.AL10(HPIO6_25A/PCLKRT6_3/DP1_DM8)
LED_7: R684.2 U3.AL11(HPIO6_25B/PCLKRC6_3)
LED_8: R520.2 U3.AN15(HPIO6_5B/DP1_DQSN6)
LED_9: R522.2 U3.AH17(HPIO6_6A/DP1_DQ41)
LED_10: R525.2 U3.AG17(HPIO6_6B/DP1_DQ40)
LED_11: R527.2 U3.AM14(HPIO6_7A/DP1_DQ49)
LED_12: R530.2 U3.AL14(HPIO6_7B/DP1_DQ48)
LED_13: R531.2 U3.AK17(HPIO6_8A/DP1_DQ45)
LED_14: R534.2 U3.AJ17(HPIO6_8B/DP1_DQ44)
LED_15: R535.2 U3.AN14(HPIO6_9A/DP1_DQ53)
PTM_SCL_18: U3.AE15(HPIO6_24A/PCLKRT6_2/DP1_DM7) U46.2(A1)
PTM_SCL_33: U46.13(B1) ; also on sheet 19
PTM_SDA_18: U3.AD15(HPIO6_24B/PCLKRC6_2) U46.3(A2)
PTM_SDA_33: U46.12(B2) ; also on sheet 19
PUSHBUTTON1: C21.1 PB1.1(TP) R21.2 R23.1 U3.AC17(HPIO6_4A/DP1_DQS5)
PUSHBUTTON2: C26.1 PB2.1(TP) R47.2 R50.1 U3.AC16(HPIO6_4B/DP1_DQSN5)
PUSHBUTTON3: C27.1 PB3.1(TP) R48.2 R51.1 U3.AP15(HPIO6_5A/DP1_DQS6)
short_stub_trace: ST.1 U3.AN10(HPIO6_21B/DP1_DQ64) U3.AN11(HPIO6_21A/DP1_DQ65)
VFMC1_3V30: F1_3V3.1(TP) ; also on sheet 7
VFMC1_3V30AUX: F1_3V3AUX.1(TP) ; also on sheet 7
VFMC1_ADJ: F1_ADJ.1(TP) ; also on sheet 7 14
VFMC2_3V30: C556.1 C557.1 C559.1 C565.1 F2_3V3.1(TP) FB24.2 J54.C39(3P3V) J54.D36(3P3V) J54.D38(3P3V) J54.D40(3P3V) L10.2 R305.1 R307.2 VFMC2_3V30.1
VFMC2_3V30AUX: C621.2 F2_3V3AUX.1(TP) FB24.1 J54.D32(3P3VAUX) R323.2 R324.2
VFMC2_ADJ: C622.1 C624.1 C628.1 C629.1 C630.1 F2_ADJ.1(TP) J54.E39(VADJ) J54.F40(VADJ) J54.G39(VADJ) J54.H40(VADJ) L14.2 R402.2 VFMC2_ADJ.1(TP) ; also on sheet 14
N20943247: JP40.1 U3.AF18(HPIO7_12A/VREF7/DP1_VREF7)
N20953373: C564.2 L10.1 U32.6(SW)
N20953565: C559.2 R305.2 R306.1 U32.2(FB)
N20953569: C564.1 U32.7(BOOT)
N20953725: C563.1 U32.4(SS)
N20953727: C562.1 U32.3(VREG)
N20954035: J54.B1(RES1) R308.1
N20954045: J54.B40(RES0) R309.1
N20954331: J54.K1(VREF_B_M2C) TP_FMC2_VREFB.1(TP)
N21072310: R23.2 SW1.2(B1) SW1.4(B2)
N21110155: R50.2 SW4.2(B1) SW4.4(B2)
N21111210: R51.2 SW5.2(B1) SW5.4(B2)
N21236832: C624.2 R402.1 R406.2 U115.6(FB)
N21319599: R655.1 R709.1 U3.AF17(EXT_RES7/DP1_EXT_RES7)
N21425635: D22.A R521.1
N21425658: D22.K(C) Q16.C
N21425660: Q16.B R520.1
N21425855: D23.A R523.1
N21425865: D23.K(C) Q17.C
N21425867: Q17.B R522.1
N21436938: D24.A R524.1
N21436944: D24.K(C) Q18.C
N21437139: Q18.B R525.1
N21437250: D25.A R526.1
N21437256: D25.K(C) Q19.C
N21437449: Q19.B R527.1
N21437528: D26.A R528.1
N21437532: D26.K(C) Q20.C
N21437655: D27.A R529.1
N21437659: D27.K(C) Q21.C
N21437864: Q20.B R530.1
N21437895: Q21.B R531.1
N21438194: D28.A R532.1
N21438198: D28.K(C) Q22.C
N21438325: D29.A R533.1
N21438329: D29.K(C) Q23.C
N21438561: Q22.B R534.1
N21438597: Q23.B R535.1
N21460625: R656.1 R710.1 U3.AF23(EXT_RES8/DP1_EXT_RES8)
N21460772: JP42.1 U3.AF24(HPIO8_12A/VREF8/DP1_VREF8)
N21970187: R245.1 U46.15(EPad)
N22581142: C1220.2 R628.1 R629.1 U115.5(EN)
N22599585: L14.1 U115.2(SW)
N22778691: J54.K40(VIO_B_M2C-2) TP_M2C_B_2_2.1(TP)
N22778693: J54.J39(VIO_B_M2C-1) TP_M2C_B_2_1.1(TP)
N23028314: AP14.1(TP) U46.11(B3)
N23030072: D12.K(CATHODE) Q27.C
N23030074: D13.K(CATHODE) Q28.C
N23030106: D12.A(ANODE) R62.1
N23030124: D13.A(ANODE) R63.1
N23030387: Q27.B R683.1
N23030530: Q28.B R684.1

Not connected (* = marked no-connect by the designer): J54 A2(DP1_M2C_P)* A3(DP1_M2C_N)* A6(DP2_M2C_P)* A7(DP2_M2C_N)* A10(DP3_M2C_P)* A11(DP3_M2C_N)* A14(DP4_M2C_P)* A15(DP4_M2C_N)* A18(DP5_M2C_P)* A19(DP5_M2C_N)* A22(DP1_C2M_P)* A23(DP1_C2M_N)* A26(DP2_C2M_P)* A27(DP2_C2M_N)* A30(DP3_C2M_P)* A31(DP3_C2M_N)* A34(DP4_C2M_P)* A35(DP4_C2M_N)* A38(DP5_C2M_P)* A39(DP5_C2M_N)* B4(DP9_M2C_P)* B5(DP9_M2C_N)* B8(DP8_M2C_P)* B9(DP8_M2C_N)* B12(DP7_M2C_P)* B13(DP7_M2C_N)* B16(DP6_M2C_P)* B17(DP6_M2C_N)* B20(GBTCLK1_M2C_P)* B21(GBTCLK1_M2C_N)* B24(DP9_C2M_P)* B25(DP9_C2M_N)* B28(DP8_C2M_P)* B29(DP8_C2M_N)* B32(DP7_C2M_P)* B33(DP7_C2M_N)* B36(DP6_C2M_P)* B37(DP6_C2M_N)* C2(DP0_C2M_P)* C3(DP0_C2M_N)* C6(DP0_M2C_P)* C7(DP0_M2C_N)* D4(GBTCLK0_M2C_P)* D5(GBTCLK0_M2C_N)* E12(HA13_P)* E13(HA13_N)* E15(HA16_P)* E16(HA16_N)* E18(HA20_P)* E19(HA20_N)* E21(HB03_P)* E22(HB03_N)* E24(HB05_P)* E25(HB05_N)* E27(HB09_P)* E28(HB09_N)* E30(HB13_P)* E31(HB13_N)* E33(HB19_P)* E34(HB19_N)* E36(HB21_P)* E37(HB21_N)* F13(HA12_P)* F14(HA12_N)* F16(HA15_P)* F17(HA15_N)* F19(HA19_P)* F20(HA19_N)* F22(HB02_P)* F23(HB02_N)* F25(HB04_P)* F26(HB04_N)* F28(HB08_P)* F29(HB08_N)* F31(HB12_P)* F32(HB12_N)* F34(HB16_P)* F35(HB16_N)* F37(HB20_P)* F38(HB20_N)* J15(HA14_P)* J16(HA14_N)* J18(HA18_P)* J19(HA18_N)* J21(HA22_P)* J22(HA22_N)* J24(HB01_P)* J25(HB01_N)* J27(HB07_P)* J28(HB07_N)* J30(HB11_P)* J31(HB11_N)* J33(HB15_P)* J34(HB15_N)* J36(HB18_P)* J37(HB18_N)* K16(HA17_P_CC)* K17(HA17_N_CC)* K19(HA21_P)* K20(HA21_N)* K22(HA23_P)* K23(HA23_N)* K25(HB00_P_CC)* K26(HB00_N_CC)* K28(HB06_P_CC)* K29(HB06_N_CC)* K31(HB10_P)* K32(HB10_N)* K34(HB14_~{P})* K35(HB14_N)* K37(HB17_P_CC)* K38(HB17_N_CC)*; U46 5(A4)* 6(NC)* 9(NC1)* 10(B4)*

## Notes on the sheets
sheet 8
- Switch Signal Map
- U3 pin
- Signal
- SWITCH
- AA16
- DIP_SW1
- 1
- DIP SWITCH
- AA17
- DIP_SW2
- 2
- AL16
- DIP_SW3
- 3
- AM16
- DIP_SW4
- 4
- AB16
- DIP_SW5
- 5
- AB17
- DIP_SW6
- 6
- AP16
- DIP_SW7
- 7
- AN16
- DIP_SW8
- 8
- LEDs Signal Map
- U3 pin
- Signal
- LED
- AL10
- LED_6
- D12
- AL11
- LED_7
- D13
- AN15
- LED_8
- D22
- Minimize length as short as
  possible short_stub_trace.
  TP close to FPGA
- AH17
- LED_9
- D23
- AG17
- LED_10
- D24
- AM14
- LED_11
- D25
- BANK 6
  1.8V
- AL14
- LED_12
- D26
- AK17
- LED_13
- D27
- AJ17
- LED_14
- D28
- AN14
- LED_15
- D29
- Two 50 ohm Lookbacks Traces:
  6 inches and 10 inches
  Place TPs close to FPGA
- LEDs
- Through Hole Extended Area
- LVCMOS&LVDS Through Hole Extended Area
sheet 9
- Default = OPEN
- Default = OPEN
- BANK 8
  1.8V
- BANK 7
  1.8 V
- FMC2 Supported:
  LA[0:33]
  HA[0:11]
sheet 10
- Default:1.8V@4A
- Vout=0.6*(1+R402/R406)=1.8V
- Parallel FMC CFG Header
